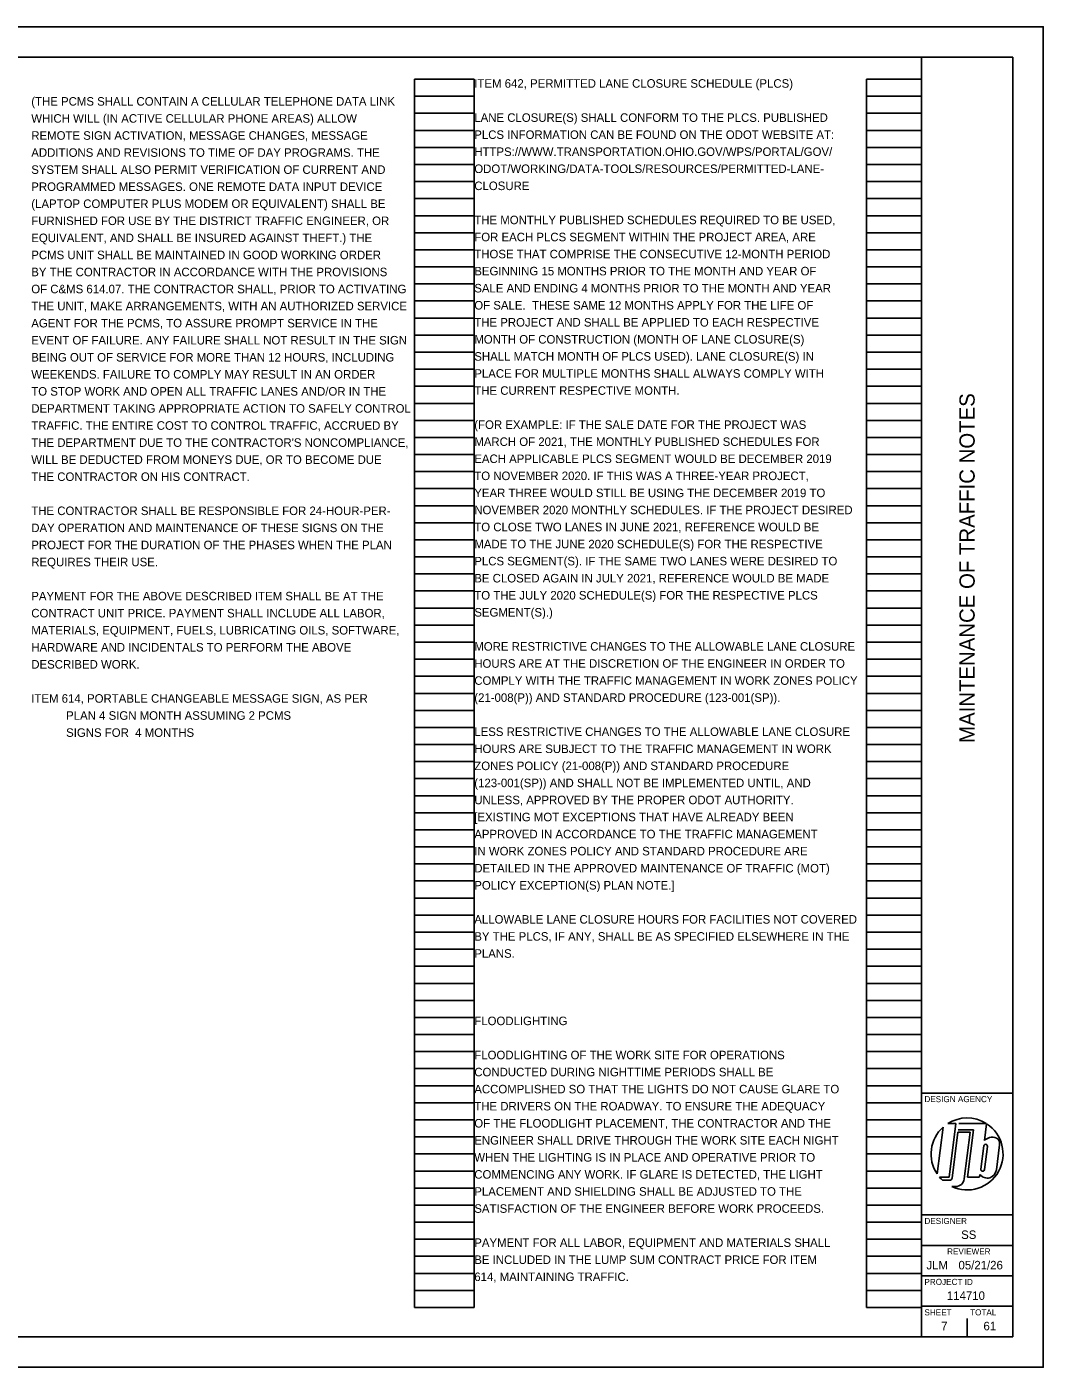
# Model space of a CAD drawing. Extents: x -6.6 to 34, y 0 to 22.
# Drawn here: x 17.31 to 34, y 0 to 22 of the extents above; entities that cross this region are included whole.
import ezdxf

# ---------------------------------------------------------------- set-up
doc = ezdxf.new("R2010")
doc.units = 0
for name, color, linetype in [('SH_Border', 7, 'Continuous'), ('SH_Cut_Line', 7, 'Continuous'), ('SH_Data', 7, 'Continuous'), ('SH_Text', 7, 'Continuous')]:
    doc.layers.add(name, color=color, linetype=linetype)

msp = doc.modelspace()

# ---------------------------------------------------------------- linework, layer by layer
at = {"layer": 'SH_Border'}
for p, q in [((32, 0.5), (32, 21.5)), ((32, 4.5), (33.5, 4.5)), ((32, 2.5), (33.5, 2.5)), ((32, 2), (33.5, 2)), ((32, 1.5), (33.5, 1.5)), ((32, 1), (33.5, 1))]:
    msp.add_line(p, q, dxfattribs=at)
msp.add_lwpolyline([(1.5, 21.5), (33.5, 21.5), (33.5, 0.5), (1.5, 0.5)], close=True, dxfattribs=at)
at = {"layer": 'SH_Cut_Line'}
msp.add_lwpolyline([(0, 0), (34, 0), (34, 22), (0, 22)], close=True, dxfattribs=at)
at = {"layer": 'SH_Data'}
for p, q in [((23.68, 0.98), (23.68, 21.14)), ((23.68, 21.14), (24.66, 21.14)), ((24.66, 0.98), (24.66, 21.14)), ((31.1, 0.98), (31.1, 21.14)), ((31.1, 21.14), (32, 21.14)), ((32, 0.98), (32, 21.14)), ((23.68, 20.86), (24.66, 20.86)), ((31.1, 20.86), (32, 20.86)), ((23.68, 20.58), (24.66, 20.58)), ((31.1, 20.58), (32, 20.58)), ((23.68, 20.3), (24.66, 20.3)), ((31.1, 20.3), (32, 20.3)), ((23.68, 20.02), (24.66, 20.02)), ((31.1, 20.02), (32, 20.02)), ((23.68, 19.74), (24.66, 19.74)), ((31.1, 19.74), (32, 19.74)), ((23.68, 19.46), (24.66, 19.46)), ((31.1, 19.46), (32, 19.46)), ((23.68, 19.18), (24.66, 19.18)), ((31.1, 19.18), (32, 19.18)), ((23.68, 18.9), (24.66, 18.9)), ((31.1, 18.9), (32, 18.9)), ((23.68, 18.62), (24.66, 18.62)), ((31.1, 18.62), (32, 18.62)), ((23.68, 18.34), (24.66, 18.34)), ((31.1, 18.34), (32, 18.34)), ((23.68, 18.06), (24.66, 18.06)), ((31.1, 18.06), (32, 18.06)), ((23.68, 17.78), (24.66, 17.78)), ((31.1, 17.78), (32, 17.78)), ((23.68, 17.5), (24.66, 17.5)), ((31.1, 17.5), (32, 17.5)), ((23.68, 17.22), (24.66, 17.22)), ((31.1, 17.22), (32, 17.22)), ((23.68, 16.94), (24.66, 16.94)), ((31.1, 16.94), (32, 16.94)), ((23.68, 16.66), (24.66, 16.66)), ((31.1, 16.66), (32, 16.66)), ((23.68, 16.38), (24.66, 16.38)), ((31.1, 16.38), (32, 16.38)), ((23.68, 16.1), (24.66, 16.1)), ((31.1, 16.1), (32, 16.1)), ((23.68, 15.82), (24.66, 15.82)), ((31.1, 15.82), (32, 15.82)), ((23.68, 15.54), (24.66, 15.54)), ((31.1, 15.54), (32, 15.54)), ((23.68, 15.26), (24.66, 15.26)), ((31.1, 15.26), (32, 15.26)), ((23.68, 14.98), (24.66, 14.98)), ((31.1, 14.98), (32, 14.98)), ((23.68, 14.7), (24.66, 14.7)), ((31.1, 14.7), (32, 14.7)), ((23.68, 14.42), (24.66, 14.42)), ((31.1, 14.42), (32, 14.42)), ((23.68, 14.14), (24.66, 14.14)), ((31.1, 14.14), (32, 14.14)), ((23.68, 13.86), (24.66, 13.86)), ((31.1, 13.86), (32, 13.86)), ((23.68, 13.58), (24.66, 13.58)), ((31.1, 13.58), (32, 13.58)), ((23.68, 13.3), (24.66, 13.3)), ((31.1, 13.3), (32, 13.3)), ((23.68, 13.02), (24.66, 13.02)), ((31.1, 13.02), (32, 13.02)), ((23.68, 12.74), (24.66, 12.74)), ((31.1, 12.74), (32, 12.74)), ((23.68, 12.46), (24.66, 12.46)), ((31.1, 12.46), (32, 12.46)), ((23.68, 12.18), (24.66, 12.18)), ((31.1, 12.18), (32, 12.18)), ((23.68, 11.9), (24.66, 11.9)), ((31.1, 11.9), (32, 11.9)), ((23.68, 11.62), (24.66, 11.62)), ((31.1, 11.62), (32, 11.62)), ((23.68, 11.34), (24.66, 11.34)), ((31.1, 11.34), (32, 11.34)), ((23.68, 11.06), (24.66, 11.06)), ((31.1, 11.06), (32, 11.06)), ((23.68, 10.78), (24.66, 10.78)), ((31.1, 10.78), (32, 10.78)), ((23.68, 10.5), (24.66, 10.5)), ((31.1, 10.5), (32, 10.5)), ((23.68, 10.22), (24.66, 10.22)), ((31.1, 10.22), (32, 10.22)), ((23.68, 9.94), (24.66, 9.94)), ((31.1, 9.94), (32, 9.94)), ((23.68, 9.66), (24.66, 9.66)), ((31.1, 9.66), (32, 9.66)), ((23.68, 9.38), (24.66, 9.38)), ((31.1, 9.38), (32, 9.38)), ((23.68, 9.1), (24.66, 9.1)), ((31.1, 9.1), (32, 9.1)), ((23.68, 8.82), (24.66, 8.82)), ((31.1, 8.82), (32, 8.82)), ((23.68, 8.54), (24.66, 8.54)), ((31.1, 8.54), (32, 8.54)), ((23.68, 8.26), (24.66, 8.26)), ((31.1, 8.26), (32, 8.26)), ((23.68, 7.98), (24.66, 7.98)), ((31.1, 7.98), (32, 7.98)), ((23.68, 7.7), (24.66, 7.7)), ((31.1, 7.7), (32, 7.7)), ((23.68, 7.42), (24.66, 7.42)), ((31.1, 7.42), (32, 7.42)), ((23.68, 7.14), (24.66, 7.14)), ((31.1, 7.14), (32, 7.14)), ((23.68, 6.86), (24.66, 6.86)), ((31.1, 6.86), (32, 6.86)), ((23.68, 6.58), (24.66, 6.58)), ((31.1, 6.58), (32, 6.58)), ((23.68, 6.3), (24.66, 6.3)), ((31.1, 6.3), (32, 6.3)), ((23.68, 6.02), (24.66, 6.02)), ((31.1, 6.02), (32, 6.02)), ((23.68, 5.74), (24.66, 5.74)), ((31.1, 5.74), (32, 5.74)), ((23.68, 5.46), (24.66, 5.46)), ((31.1, 5.46), (32, 5.46)), ((23.68, 5.18), (24.66, 5.18)), ((31.1, 5.18), (32, 5.18)), ((23.68, 4.9), (24.66, 4.9)), ((31.1, 4.9), (32, 4.9)), ((23.68, 4.62), (24.66, 4.62)), ((31.1, 4.62), (32, 4.62)), ((23.68, 4.34), (24.66, 4.34)), ((31.1, 4.34), (32, 4.34)), ((23.68, 4.06), (24.66, 4.06)), ((31.1, 4.06), (32, 4.06)), ((32.432, 3.998), (32.567, 3.998)), ((32.567, 3.998), (32.456, 3.118)), ((32.617, 4), (33.065, 4)), ((33.07, 3.996), (33.035, 3.72)), ((23.68, 3.78), (24.66, 3.78)), ((31.1, 3.78), (32, 3.78)), ((32.356, 3.94), (32.259, 3.171)), ((32.504, 3.104), (32.599, 3.855)), ((32.599, 3.855), (32.801, 3.855)), ((32.856, 3.896), (32.604, 3.896)), ((32.801, 3.855), (32.704, 3.089)), ((32.758, 3.118), (32.856, 3.896)), ((33.024, 3.631), (32.976, 3.25)), ((33.036, 3.243), (33.084, 3.624)), ((33.283, 3.648), (33.231, 3.237)), ((23.68, 3.5), (24.66, 3.5)), ((31.1, 3.5), (32, 3.5)), ((32.75, 3.5), (32.75, 3.5)), ((23.68, 3.22), (24.66, 3.22)), ((31.1, 3.22), (32, 3.22)), ((32.456, 3.118), (32.299, 3.118)), ((32.947, 3.118), (32.758, 3.118)), ((32.964, 3.161), (32.947, 3.118)), ((23.68, 2.94), (24.66, 2.94)), ((31.1, 2.94), (32, 2.94)), ((32.347, 3.068), (32.462, 3.068)), ((32.564, 2.966), (32.498, 2.966)), ((23.68, 2.66), (24.66, 2.66)), ((31.1, 2.66), (32, 2.66)), ((23.68, 2.38), (24.66, 2.38)), ((31.1, 2.38), (32, 2.38)), ((23.68, 2.1), (24.66, 2.1)), ((31.1, 2.1), (32, 2.1)), ((23.68, 1.82), (24.66, 1.82)), ((31.1, 1.82), (32, 1.82)), ((23.68, 1.54), (24.66, 1.54)), ((31.1, 1.54), (32, 1.54)), ((23.68, 1.26), (24.66, 1.26)), ((31.1, 1.26), (32, 1.26)), ((23.68, 0.98), (24.66, 0.98)), ((31.1, 0.98), (32, 0.98)), ((32.375, 0.675), (32.375, 0.675)), ((32.75, 0.5), (32.75, 0.8))]:
    msp.add_line(p, q, dxfattribs=at)
for centre, radius, start, end in [((32.75, 3.5), 0.591, 57.726, 122.5688), ((32.75, 3.5), 0.591, 244.7646, 57.1575), ((32.75, 3.5), 0.591, 131.8253, 213.7822), ((33.17, 3.586), 0.19, 105.9444, 135.0487), ((33.164, 3.6), 0.175, 66.6782, 105.4185), ((33.177, 3.669), 0.108, 349.2072, 58.7163), ((33.054, 3.628), 0.0301, 352.3298, 173.2777), ((32.75, 3.5), 0.591, 220.2786, 227.0158), ((32.462, 3.109), 0.0417, 270, 352.8038), ((32.564, 3.106), 0.141, 270, 352.8038), ((33.081, 3.255), 0.151, 218.6264, 353.0883), ((33.006, 3.246), 0.0301, 172.3335, 353.274)]:
    msp.add_arc(centre, radius, start, end, dxfattribs=at)

# ---------------------------------------------------------------- texts
msp.add_text('MAINTENANCE OF TRAFFIC NOTES', height=0.25, rotation=90, dxfattribs=at).set_placement((32.875, 10.247))
for s, height, p in [('DESIGN AGENCY', 0.1, (32.05, 4.35)), ('DESIGNER', 0.1, (32.05, 2.35)), ('SS', 0.14, (32.653, 2.105)), ('REVIEWER', 0.1, (32.422, 1.85)), ('JLM', 0.14, (32.083, 1.605)), ('05/21/26', 0.14, (32.609, 1.605)), ('PROJECT ID', 0.1, (32.05, 1.35)), ('114710', 0.14, (32.419, 1.105)), ('SHEET', 0.1, (32.05, 0.85)), ('TOTAL', 0.1, (32.8, 0.85)), ('7', 0.14, (32.324, 0.605)), ('61', 0.14, (33.019, 0.605))]:
    msp.add_text(s, height=height, dxfattribs=at).set_placement(p)
at = {"layer": 'SH_Text'}
for s, p in [('ITEM 642, PERMITTED LANE CLOSURE SCHEDULE (PLCS)', (24.66, 21)), ('(THE PCMS SHALL CONTAIN A CELLULAR TELEPHONE DATA LINK', (17.387, 20.706)), ('WHICH WILL (IN ACTIVE CELLULAR PHONE AREAS) ALLOW', (17.387, 20.426)), ('LANE CLOSURE(S) SHALL CONFORM TO THE PLCS. PUBLISHED', (24.66, 20.44)), ('REMOTE SIGN ACTIVATION, MESSAGE CHANGES, MESSAGE', (17.387, 20.146)), ('PLCS INFORMATION CAN BE FOUND ON THE ODOT WEBSITE AT:', (24.66, 20.16)), ('HTTPS://WWW.TRANSPORTATION.OHIO.GOV/WPS/PORTAL/GOV/', (24.66, 19.88)), ('ADDITIONS AND REVISIONS TO TIME OF DAY PROGRAMS. THE', (17.387, 19.866)), ('SYSTEM SHALL ALSO PERMIT VERIFICATION OF CURRENT AND', (17.387, 19.586)), ('ODOT/WORKING/DATA-TOOLS/RESOURCES/PERMITTED-LANE-', (24.66, 19.6)), ('PROGRAMMED MESSAGES. ONE REMOTE DATA INPUT DEVICE', (17.387, 19.306)), ('CLOSURE', (24.66, 19.32)), ('(LAPTOP COMPUTER PLUS MODEM OR EQUIVALENT) SHALL BE', (17.387, 19.026)), ('FURNISHED FOR USE BY THE DISTRICT TRAFFIC ENGINEER, OR', (17.387, 18.746)), ('THE MONTHLY PUBLISHED SCHEDULES REQUIRED TO BE USED,', (24.66, 18.76)), ('EQUIVALENT, AND SHALL BE INSURED AGAINST THEFT.) THE', (17.387, 18.466)), ('FOR EACH PLCS SEGMENT WITHIN THE PROJECT AREA, ARE', (24.66, 18.48)), ('PCMS UNIT SHALL BE MAINTAINED IN GOOD WORKING ORDER', (17.387, 18.186)), ('THOSE THAT COMPRISE THE CONSECUTIVE 12-MONTH PERIOD', (24.66, 18.2)), ('BY THE CONTRACTOR IN ACCORDANCE WITH THE PROVISIONS', (17.387, 17.906)), ('BEGINNING 15 MONTHS PRIOR TO THE MONTH AND YEAR OF', (24.66, 17.92)), ('OF C&MS 614.07. THE CONTRACTOR SHALL, PRIOR TO ACTIVATING', (17.387, 17.626)), ('SALE AND ENDING 4 MONTHS PRIOR TO THE MONTH AND YEAR', (24.66, 17.64)), ('THE UNIT, MAKE ARRANGEMENTS, WITH AN AUTHORIZED SERVICE', (17.387, 17.346)), ('OF SALE.  THESE SAME 12 MONTHS APPLY FOR THE LIFE OF', (24.66, 17.36)), ('AGENT FOR THE PCMS, TO ASSURE PROMPT SERVICE IN THE', (17.387, 17.066)), ('THE PROJECT AND SHALL BE APPLIED TO EACH RESPECTIVE', (24.66, 17.08)), ('MONTH OF CONSTRUCTION (MONTH OF LANE CLOSURE(S)', (24.66, 16.8)), ('EVENT OF FAILURE. ANY FAILURE SHALL NOT RESULT IN THE SIGN', (17.387, 16.786)), ('BEING OUT OF SERVICE FOR MORE THAN 12 HOURS, INCLUDING', (17.387, 16.506)), ('SHALL MATCH MONTH OF PLCS USED). LANE CLOSURE(S) IN', (24.66, 16.52)), ('WEEKENDS. FAILURE TO COMPLY MAY RESULT IN AN ORDER', (17.387, 16.226)), ('PLACE FOR MULTIPLE MONTHS SHALL ALWAYS COMPLY WITH', (24.66, 16.24)), ('TO STOP WORK AND OPEN ALL TRAFFIC LANES AND/OR IN THE', (17.387, 15.946)), ('THE CURRENT RESPECTIVE MONTH.', (24.66, 15.96)), ('DEPARTMENT TAKING APPROPRIATE ACTION TO SAFELY CONTROL', (17.387, 15.666)), ('TRAFFIC. THE ENTIRE COST TO CONTROL TRAFFIC, ACCRUED BY', (17.387, 15.386)), ('(FOR EXAMPLE: IF THE SALE DATE FOR THE PROJECT WAS', (24.66, 15.4)), ("THE DEPARTMENT DUE TO THE CONTRACTOR'S NONCOMPLIANCE,", (17.387, 15.106)), ('MARCH OF 2021, THE MONTHLY PUBLISHED SCHEDULES FOR', (24.66, 15.12)), ('WILL BE DEDUCTED FROM MONEYS DUE, OR TO BECOME DUE', (17.387, 14.826)), ('EACH APPLICABLE PLCS SEGMENT WOULD BE DECEMBER 2019', (24.66, 14.84)), ('THE CONTRACTOR ON HIS CONTRACT.', (17.387, 14.546)), ('TO NOVEMBER 2020. IF THIS WAS A THREE-YEAR PROJECT,', (24.66, 14.56)), ('YEAR THREE WOULD STILL BE USING THE DECEMBER 2019 TO', (24.66, 14.28)), ('THE CONTRACTOR SHALL BE RESPONSIBLE FOR 24-HOUR-PER-', (17.387, 13.986)), ('NOVEMBER 2020 MONTHLY SCHEDULES. IF THE PROJECT DESIRED', (24.66, 14)), ('TO CLOSE TWO LANES IN JUNE 2021, REFERENCE WOULD BE', (24.66, 13.72)), ('DAY OPERATION AND MAINTENANCE OF THESE SIGNS ON THE', (17.387, 13.706)), ('PROJECT FOR THE DURATION OF THE PHASES WHEN THE PLAN', (17.387, 13.426)), ('MADE TO THE JUNE 2020 SCHEDULE(S) FOR THE RESPECTIVE', (24.66, 13.44)), ('REQUIRES THEIR USE.', (17.387, 13.146)), ('PLCS SEGMENT(S). IF THE SAME TWO LANES WERE DESIRED TO', (24.66, 13.16)), ('BE CLOSED AGAIN IN JULY 2021, REFERENCE WOULD BE MADE', (24.66, 12.88)), ('PAYMENT FOR THE ABOVE DESCRIBED ITEM SHALL BE AT THE', (17.387, 12.586)), ('TO THE JULY 2020 SCHEDULE(S) FOR THE RESPECTIVE PLCS', (24.66, 12.6)), ('CONTRACT UNIT PRICE. PAYMENT SHALL INCLUDE ALL LABOR,', (17.387, 12.306)), ('SEGMENT(S).)', (24.66, 12.32)), ('MATERIALS, EQUIPMENT, FUELS, LUBRICATING OILS, SOFTWARE,', (17.387, 12.026)), ('HARDWARE AND INCIDENTALS TO PERFORM THE ABOVE', (17.387, 11.746)), ('MORE RESTRICTIVE CHANGES TO THE ALLOWABLE LANE CLOSURE', (24.66, 11.76)), ('DESCRIBED WORK.', (17.387, 11.466)), ('HOURS ARE AT THE DISCRETION OF THE ENGINEER IN ORDER TO', (24.66, 11.48)), ('COMPLY WITH THE TRAFFIC MANAGEMENT IN WORK ZONES POLICY', (24.66, 11.2)), ('ITEM 614, PORTABLE CHANGEABLE MESSAGE SIGN, AS PER', (17.387, 10.906)), ('(21-008(P)) AND STANDARD PROCEDURE (123-001(SP)).', (24.66, 10.92)), ('           PLAN 4 SIGN MONTH ASSUMING 2 PCMS', (17.387, 10.626)), ('           SIGNS FOR  4 MONTHS', (17.387, 10.346)), ('LESS RESTRICTIVE CHANGES TO THE ALLOWABLE LANE CLOSURE', (24.66, 10.36)), ('HOURS ARE SUBJECT TO THE TRAFFIC MANAGEMENT IN WORK', (24.66, 10.08)), ('ZONES POLICY (21-008(P)) AND STANDARD PROCEDURE', (24.66, 9.8)), ('(123-001(SP)) AND SHALL NOT BE IMPLEMENTED UNTIL, AND', (24.66, 9.52)), ('UNLESS, APPROVED BY THE PROPER ODOT AUTHORITY.', (24.66, 9.24)), ('[EXISTING MOT EXCEPTIONS THAT HAVE ALREADY BEEN', (24.66, 8.96)), ('APPROVED IN ACCORDANCE TO THE TRAFFIC MANAGEMENT', (24.66, 8.68)), ('IN WORK ZONES POLICY AND STANDARD PROCEDURE ARE', (24.66, 8.4)), ('DETAILED IN THE APPROVED MAINTENANCE OF TRAFFIC (MOT)', (24.66, 8.12)), ('POLICY EXCEPTION(S) PLAN NOTE.]', (24.66, 7.84)), ('ALLOWABLE LANE CLOSURE HOURS FOR FACILITIES NOT COVERED', (24.66, 7.28)), ('BY THE PLCS, IF ANY, SHALL BE AS SPECIFIED ELSEWHERE IN THE', (24.66, 7)), ('PLANS.', (24.66, 6.72)), ('FLOODLIGHTING', (24.66, 5.614)), ('FLOODLIGHTING OF THE WORK SITE FOR OPERATIONS', (24.66, 5.054)), ('CONDUCTED DURING NIGHTTIME PERIODS SHALL BE', (24.66, 4.774)), ('ACCOMPLISHED SO THAT THE LIGHTS DO NOT CAUSE GLARE TO', (24.66, 4.494)), ('THE DRIVERS ON THE ROADWAY. TO ENSURE THE ADEQUACY', (24.66, 4.214)), ('OF THE FLOODLIGHT PLACEMENT, THE CONTRACTOR AND THE', (24.66, 3.934)), ('ENGINEER SHALL DRIVE THROUGH THE WORK SITE EACH NIGHT', (24.66, 3.654)), ('WHEN THE LIGHTING IS IN PLACE AND OPERATIVE PRIOR TO', (24.66, 3.374)), ('COMMENCING ANY WORK. IF GLARE IS DETECTED, THE LIGHT', (24.66, 3.094)), ('PLACEMENT AND SHIELDING SHALL BE ADJUSTED TO THE', (24.66, 2.814)), ('SATISFACTION OF THE ENGINEER BEFORE WORK PROCEEDS.', (24.66, 2.534)), ('PAYMENT FOR ALL LABOR, EQUIPMENT AND MATERIALS SHALL', (24.66, 1.974)), ('BE INCLUDED IN THE LUMP SUM CONTRACT PRICE FOR ITEM', (24.66, 1.694)), ('614, MAINTAINING TRAFFIC.', (24.66, 1.414))]:
    msp.add_text(s, height=0.14, dxfattribs=at).set_placement(p)

doc.saveas('drawing.dxf')
